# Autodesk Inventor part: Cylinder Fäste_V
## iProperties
Created: 2001-12
Part Number: Cylinder Fäste_V
Material: Steel, Mild
Document SubType Name: Modeling
Designer: Tobben
Control State: 0
Master: False
Checked Out: False
Shininess: 64.0
Length Units: 11269
Angle Units: 11279
Time Units: 11290
Mass Units: 11283
Length Display Precision: 3
Angle Display Precision: 2
Density: 0.0
Volumn: 0.0
Area: 0.0
PropertySet Name: Model Information
Author: Tobben
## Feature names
1. Derived Body1 [Tagging]
